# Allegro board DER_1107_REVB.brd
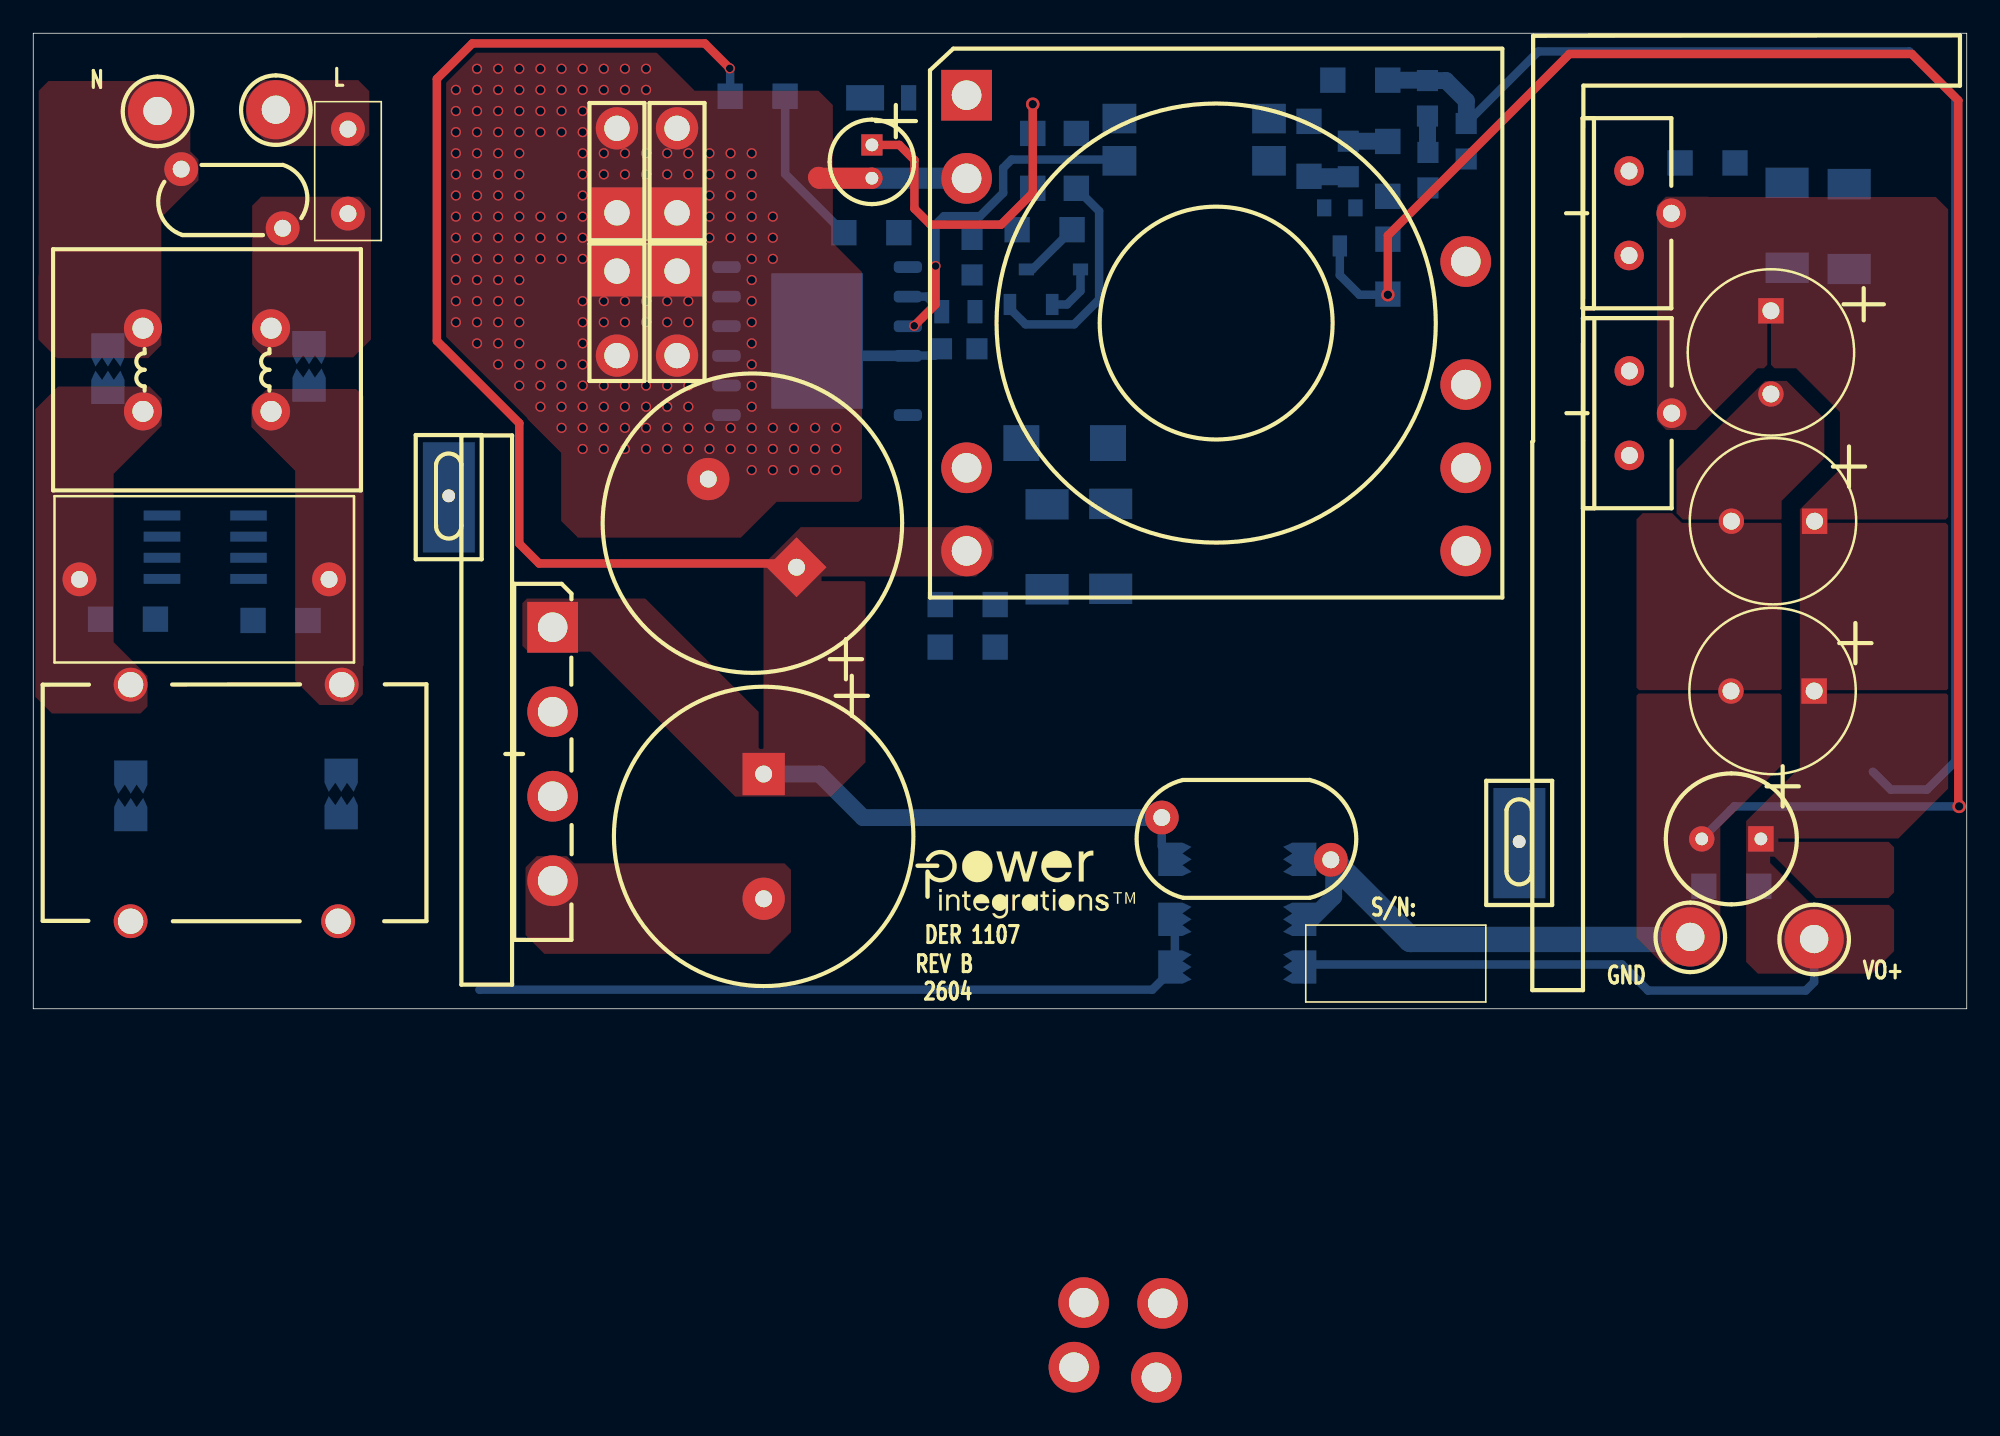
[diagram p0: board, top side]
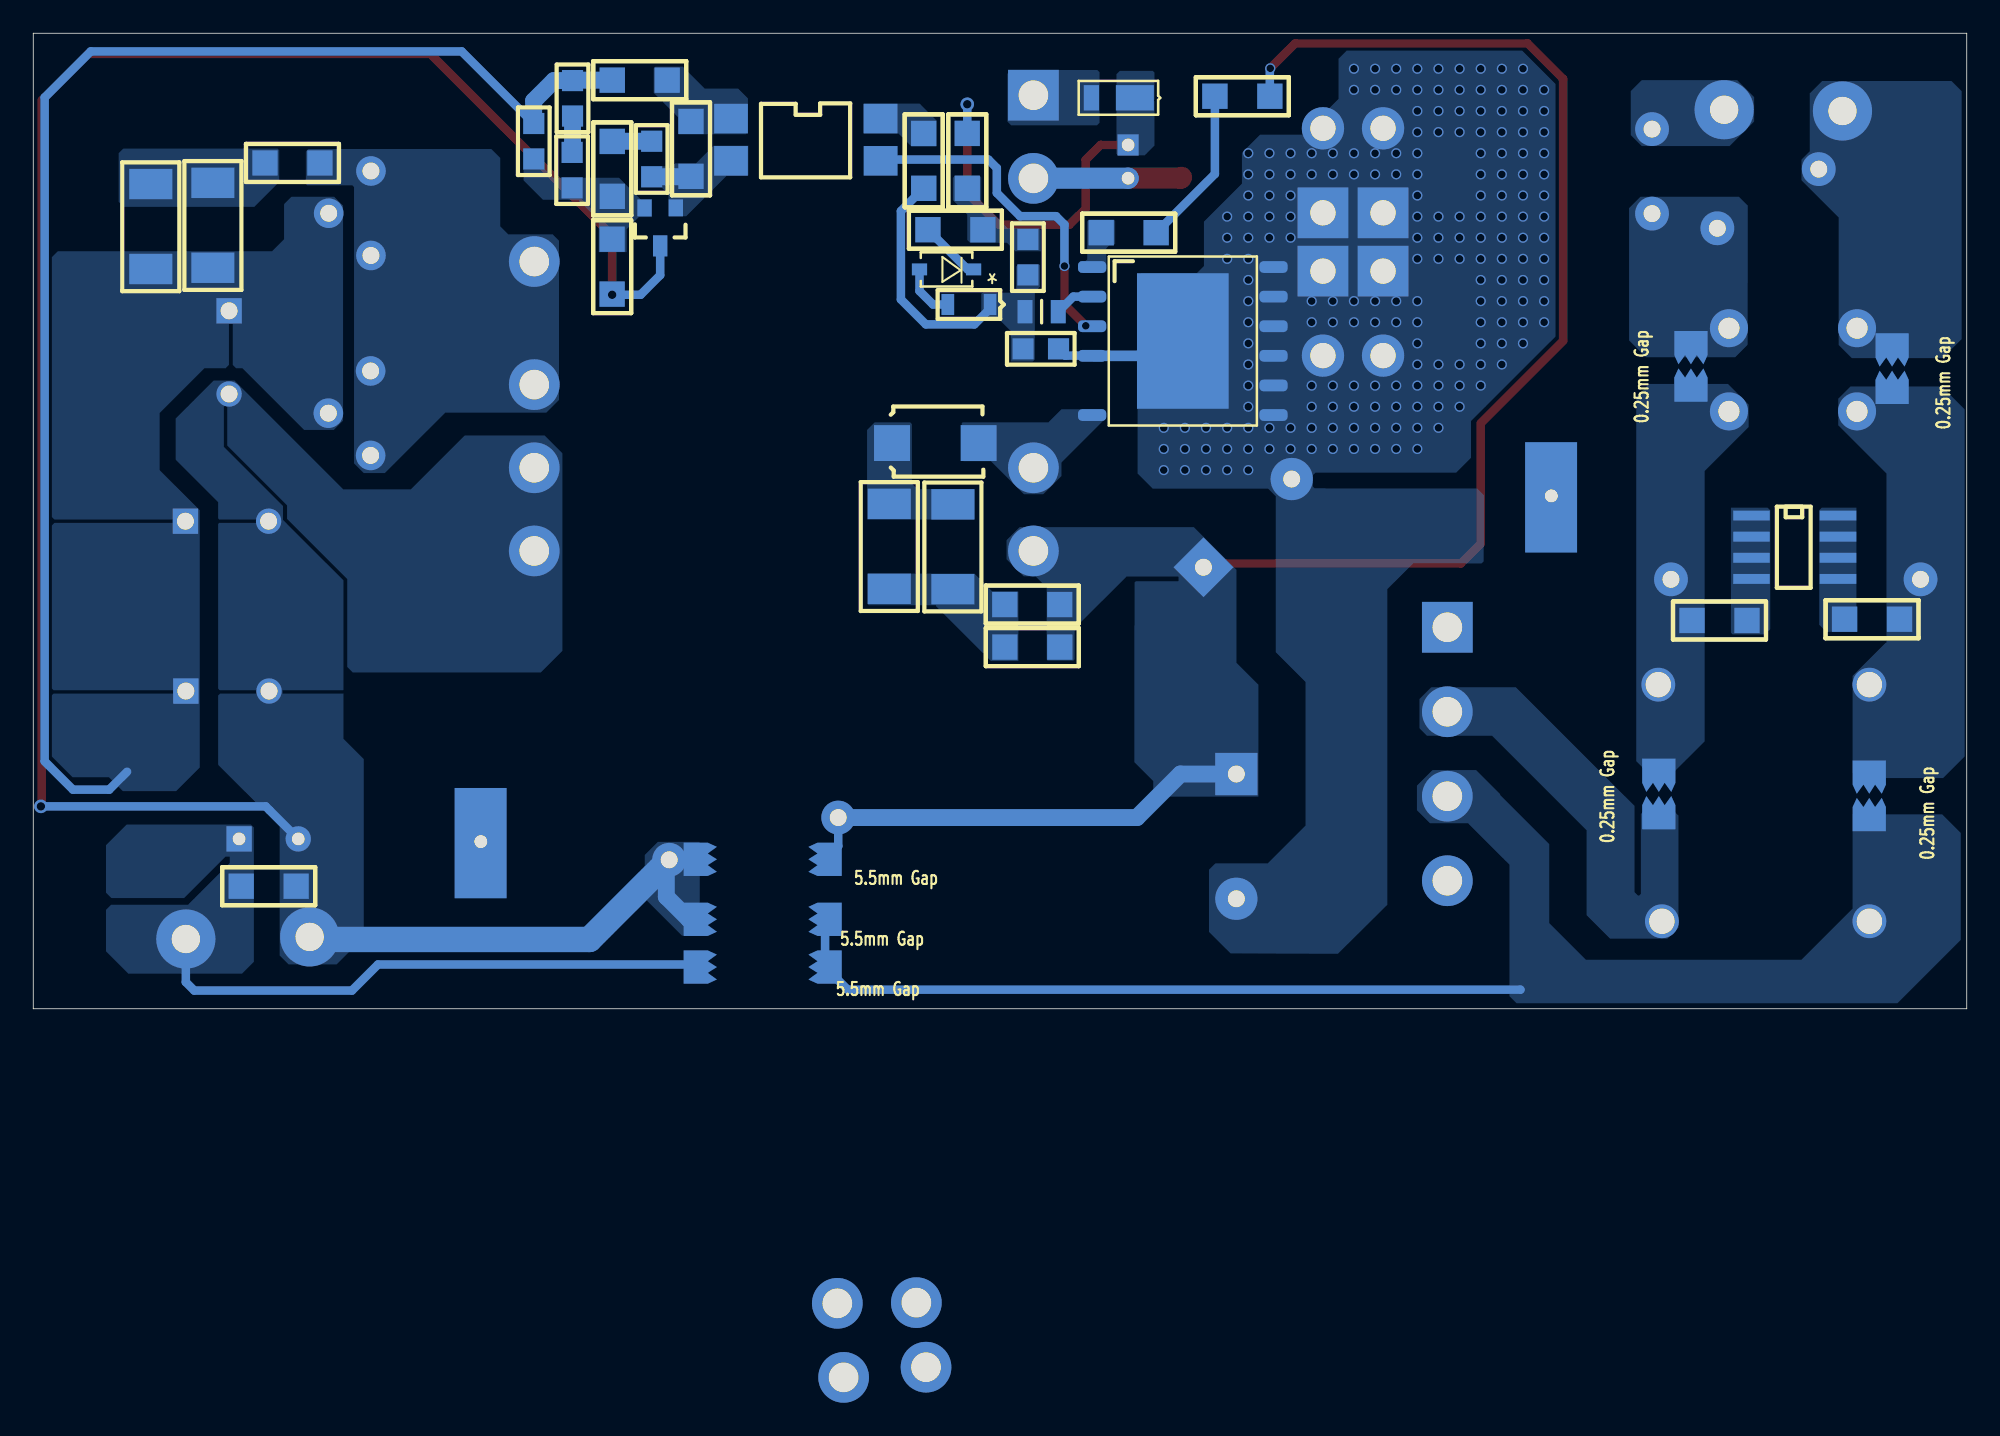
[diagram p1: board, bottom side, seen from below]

Outline 116.2 x 58.65 mm; copper layers: TOP, BOTTOM. Coordinates in mm from the lower left corner of the outline.
Outline path: 0,58.65 116.2,58.65 116.2,0 0,0 0,58.65

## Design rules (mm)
constraint set DEFAULT: min track width 0.508

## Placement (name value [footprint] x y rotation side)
BR1  GBU8K-BP  [PIDAXBRIDGEGBU8]  31.22 22.94 270 top
C1  0.68 uF  [PI_NPCAP18X10X16P1D40]  2.78 25.82 0 top
C3  180 uF  [PIPOLCAPCLYD18MM040]  43.9 10.36 270 top
C4  180 uF  [PIPOLCAPCLYD18MM040]  43.22 29.19 135 top
C6  0.47 uF  [PISMC0805]  56.72 39.67 180 bottom
C7  4700 pF  [PISMC1206]  54.51 24.3 0 bottom
C8  47 uF  [PIPOLCAPCLYD200LS80030]  50.4 51.93 270 top
C9  680 pF  [PISMC1206]  98.98 50.85 0 bottom
C10  560 uF  [PIPOLCAPCLYD10MM040]  104.44 41.96 270 top
C11  560 uF  [PIPOLCAPCLYD10MM040]  107.06 29.31 180 top
C12  10 nF  [PISMC0805]  79.04 50.02 90 bottom
C13  150 uF  [PIPOLCAPCLYD320LS140030]  103.84 10.21 180 top
C14  10 nF  [PISMC0805]  83.82 49.35 90 bottom
C15  560 uF  [PIPOLCAPCLYD10MM040]  107.04 19.1 180 top
C16  10 uF  [PISMC1206]  100.41 7.37 0 bottom
CY1  2.2 nF  [PINPYCAPRAD540X290LS400040]  67.83 11.49 0 top
D1  S2M  [PISMSMB]  64.59 34.01 180 bottom
D3  BAV21WS-7-F  [PISMSOD323]  58.7 42.34 0 bottom
D4  DFLR1200-7  [PISMDDFLR120012]  49.97 54.77 180 bottom
D5  V20202C-M3/4W  [PIDVTO2203VF1]  95.91 47.83 90 top
D6  V20202C-M3/4W  [PIDVTO2203VF1]  95.93 35.81 90 top
F1  5 A  [PI_RST_MICROFUSE]  18.91 52.89 270 top
L1  350 uH  [PIIND4P_18P5X14P5MMD050]  10.44 38.41 0 top
L2  10 mH  [PI_TOROID_BALUN_1]  18.55 5.26 90 top
L3  42 Ohm@100MHz  [INDC2012X105N]  55.6 41.91 180 bottom
NOREF  -  []  0 58.65 0 top
NOREF#2  -  []  -232.54 -144.86 0 top
NOREF#3  -  []  0 0 90 top
NOREF#4  -  []  53.04 9.98 0 top
NOREF#5  -  []  53.72 -90.37 0 top
R1  1 M  [PISMR1206]  16.51 23.34 180 bottom
R2  1 M  [PISMR1206]  7.34 23.42 180 bottom
R3  4.02M  [PISMR1206]  41.88 54.86 0 bottom
R4  4.02M  [PISMR1206]  48.72 46.66 0 bottom
R5  470 k  [PISMR1206]  54.51 21.74 0 bottom
R6  20  [PISMR2010]  60.93 25.22 90 bottom
R7  20  [PISMR2010]  64.76 25.25 90 bottom
R8  3.30 k  [PISMR0805]  56.43 46.25 270 bottom
R9  47.0  [PISMR1206]  59.13 46.84 0 bottom
R10  20  [PISMR2010]  109.14 44.48 90 bottom
R11  20  [PISMR2010]  105.41 44.55 90 bottom
R12  3.01 k  [PISMR1206]  81.41 55.83 180 bottom
R13  1.0 k  [PISMR1206]  76.67 53.35 270 bottom
R14  20.0 k  [PISMR1206]  81.41 48.84 90 bottom
R15  86.6 k  [PISMR0805]  86.12 53.22 270 bottom
R16  10 k  [PISMR1206]  81.41 46.27 270 bottom
R17  0.0  [PISMR1206]  60.07 49.33 90 bottom
R18  0.0  [PISMR1206]  62.69 49.33 90 bottom
R19  10 k  [PISMR0805]  83.79 55.8 270 bottom
RV1  275 Vac  [PIDISC350X160LS210X140040]  14.99 46.92 180 top
SG1  5.5mm gap  [PI_SPARK_GAP_5P5MM]  72.37 8.98 0 bottom
SG2  5.5mm gap  [PI_SPARK_GAP_5P5MM]  72.37 5.38 0 bottom
SG3  5.5mm gap  [PI_SPARK_GAP_5P5MM]  72.37 2.51 0 bottom
SG4  0.25mm gap  [PI_SPARK_GAP_0P25MM]  18.51 12.91 270 bottom
SG5  0.25mm gap  [PI_SPARK_GAP_0P25MM]  5.86 12.8 270 bottom
SG6  0.25mm gap  [PI_SPARK_GAP_0P25MM]  16.58 38.62 270 bottom
SG7  0.25mm gap  [PI_SPARK_GAP_0P25MM]  4.49 38.49 270 bottom
T1  PQ32/30  [PI_BBN_TDKBPQ32_30_12P]  71.09 41.22 0 top
TAB1  CON2  [PI_CONN_QC_TAB_2PIN_LS200]  38.69 47.85 0 top
TAB2  CON2  [PI_CONN_QC_TAB_2PIN_LS200]  35.08 47.85 0 top
TAB3  CON2  [PI_CONN_QC_TAB_2PIN_LS200]  35.08 44.35 180 top
TAB4  CON2  [PI_CONN_QC_TAB_2PIN_LS200]  38.69 44.35 180 top
TE1  Terminal, Eyelet, Zierick 190  [PI_ZIERICK190_EYELET]  24.97 30.84 90 top
TE2  Terminal, Eyelet, Zierick 190  [PI_ZIERICK190_EYELET]  89.31 10.05 90 top
TP1  BLK  [PITPKEYSTONE125X125]  14.58 54.05 0 top
TP2  WHT  [PITPKEYSTONE125X125]  7.47 53.98 0 top
TP3  RED  [PITPKEYSTONE125X125]  107.04 4.19 0 top
TP4  BLK  [PITPKEYSTONE125X125]  99.59 4.32 0 top
U1  CAP200DG  [PI_IC_SMD_SO8_CAPZERO]  12.94 29.65 270 bottom
U2  TOP7078K  [PI_ESOP-12B]  47.11 40.14 270 bottom
U3  LTV-817S-D  [PI_4_SMD_GW_1]  74.27 53.52 270 bottom
U4  LM431BIM3/NOPB  [PISMSOT23123]  79.47 48.15 0 bottom
VR1  MMSZ5246BT1G  [PISM_SOD-123]  61.32 44.45 0 bottom

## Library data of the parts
BR1 = DISCRETE BRIDGE_+~~-: alternate symbols: (pidaxbridgegbu8_horz)
C1 = CAP NP: alternate symbols: (pi_npcap18x10x16p1D40H); room: 1
C3 C4 = CAP POL: alternate symbols: (pipolcapclyd18x40mm040)
C6 C12 C14 = CAP NP: alternate symbols: (Unisem_RMCF0805UL)
C7 C9 = CAP NP: tolerance: 10
C8 = CAP POL: alternate symbols: (pipolcapclyd200ls80030h); tolerance: 20
C10 C11 C15 = CAP POL: alternate symbols: (pipolcapcyld400ls2000401000h)
C13 = CAP POL: alternate symbols: (pipolcapclyd320ls140030430h); tolerance: 20
C16 = CAP NP: alternate symbols: (pismc1206_1)
CY1 = CAP NP
D1 D4 = DIODE
D3 = DIODE: alternate symbols: (SOD323_UL_IPC,pismsod323_1)
D5 D6 = DS_DUAL_CK_AKA: alternate symbols: (pidvto2203,pidvto2203h)
F1 = FUSE: alternate symbols: (pirstmicrofusehoz); room: 1
L1 = CMC_ 4P_14_23
L2 = TORRID 4P_12_34
L3 = INDUCTOR_BEAD
R1 R2 R5-R7 R9-R14 R16-R18 = R
R3 R4 = R: alternate symbols: (pismr1206_1)
R8 R15 R19 = R: alternate symbols: (Unisem_RMCF0805UL)
RV1 = VARISTOR: alternate symbols: (pi_disc_354x220_ls220x10_040_h); room: 1
SG1-SG7 = SPARK_GAP
T1 = BPQ32/30_12P/GENERIC
TAB1-TAB4 = CON1_2P_TAB
TE1 TE2 = TERM EYLT
TP1-TP4 = TESTPOINT: alternate symbols: (TP_5010-14)
U1 = CAPZero: room: 1
U2 = TOPSwitch-GaN_eSOP12B
U3 = OPTO_A_B: alternate symbols: (pi_4_smd_gw)
U4 = TL431/SOT-23_CAR
VR1 = DIODE_ZENER

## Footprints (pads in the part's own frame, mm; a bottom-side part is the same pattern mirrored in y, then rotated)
INDC2012X105N
  rect 0.9x1.4 smd: 1(-1,0) 2(1,0)
PI_4_SMD_GW_1
  rect 1.778x2.032 smd: 1(0,0) 2(2.54,0) 3(2.54,8.992) 4(0,8.992)
PI_BBN_TDKBPQ32_30_12P
  rect 3.048x3.048 hole 1.778: 1(-15,13.7)
  round 3.048 hole 1.778: 2(-15,8.7) 3(-3.214,-58.936) 4(-7.964,-58.894) 5(-15,-8.7) 6(-15,-13.7) 7(15,-13.7) 8(15,-8.7) 9(15,-3.7) 10(15,3.7) 11(-8.546,-62.776) 12(-3.593,-63.389)
PI_CONN_QC_TAB_2PIN_LS200
  rect 3.048x3.048 hole 1.524: 1(0,0)
  round 2.54 hole 1.524: 2(0,5.08)
PI_ESOP-12B
  rrect 0.71x1.7 smd: 1(-4.45,-5.45) 2(-2.67,-5.45) 3(-0.89,-5.45) 4(0.89,-5.45) 6(4.45,-5.45) 7(4.45,5.45) 8(2.67,5.45) 9(0.89,5.45) 10(-0.89,5.45) 11(-2.67,5.45) 12(-4.45,5.45)
  rect 8.15x5.51 smd: 13(0,0)
PI_IC_SMD_SO8_CAPZERO
  rect 0.599x2.2 smd: 1(0,0) 2(1.27,0) 3(2.54,0) 4(3.81,0) 5(3.81,5.199) 6(2.54,5.199) 7(1.27,5.199) 8(0,5.199)
PI_NPCAP18X10X16P1D40
  round 2.032 hole 1.016: 1(0,0) 2(15,0)
PI_RST_MICROFUSE
  round 2.032 hole 1.016: 1(0,0) 2(5.08,0)
PI_SPARK_GAP_0P25MM
  custom 0.5x0.5 smd: 1(-1.125,0) 2(1.125,0)
PI_SPARK_GAP_5P5MM
  custom 0.5x0.5 smd: 1(-3.75,0) 2(3.75,0)
PI_TOROID_BALUN_1
  round 2.032 hole 1.524: 1(14.224,0.013) 2(0,0.229) 3(14.224,12.7) 4(0,12.7)
PI_ZIERICK190_EYELET
  round 0.762 hole 0.762: 1(0,0)
PIDAXBRIDGEGBU8
  rect 3.048x3.048 hole 1.778: 1(0,0)
  round 3.048 hole 1.778: 2(5.08,0) 3(10.16,0) 4(15.24,0)
PIDISC350X160LS210X140040
  round 2.032 hole 1.016: 1(0,0) 2(6.096,-3.556)
PIDVTO2203VF1
  round 1.778 hole 1.016: 1(-2.54,0) 2(0,-2.54) 3(2.54,0)
PIIND4P_18P5X14P5MMD050
  round 2.286 hole 1.27: 1(-3.85,-2.5) 2(3.85,-2.5) 3(3.85,2.5) 4(-3.85,2.5)
PINPYCAPRAD540X290LS400040
  round 2.032 hole 1.016: 1(0,0) 2(10.16,-2.54)
PIPOLCAPCLYD10MM040
  rect 1.524x1.524 hole 1.016: 1(0,0)
  round 1.524 hole 1.016: 2(5,0)
PIPOLCAPCLYD18MM040
  rect 2.54x2.54 hole 1.016: 1(-3.75,0)
  round 2.54 hole 1.016: 2(3.75,0)
PIPOLCAPCLYD200LS80030
  rect 1.27x1.27 hole 0.762: 1(0,0)
  round 1.27 hole 0.762: 2(2,0)
PIPOLCAPCLYD320LS140030
  rect 1.524x1.524 hole 0.762: 1(0,0)
  round 1.524 hole 0.762: 2(3.556,0)
PISM_SOD-123
  rect 0.914x0.711 smd: 1(-1.626,0) 2(1.626,0)
PISMC0805
  rect 1.27x1.27 smd: 1(0,0) 2(2.134,0)
PISMC1206
  rect 1.524x1.524 smd: 1(0,0) 2(3.302,0)
PISMDDFLR120012
  rect 2.286x1.524 smd: 1(-0.025,0)
  rect 0.914x1.524 smd: 2(-2.642,0)
PISMR0805
  rect 1.27x1.27 smd: 1(0,0) 2(2.134,0)
PISMR1206
  rect 1.524x1.524 smd: 1(0,0) 2(3.302,0)
PISMR2010
  rect 1.829x2.591 smd: 1(0,0) 2(5.105,0)
PISMSMB
  rect 2.159x2.159 smd: 1(0,0) 2(5.207,0)
PISMSOD323
  rect 0.762x1.27 smd: 1(0,0) 2(2.54,0)
PISMSOT23123
  rect 0.864x1.016 smd: 1(-1.88,0) 3(0,0)
  rect 0.864x1.27 smd: 2(-0.94,2.286)
PITPKEYSTONE125X125
  round 3.556 hole 1.702: 1(0,0)

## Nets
PGND: BR1.4 C3.2 C4.2 C6.2 C8.2 T1.2 TAB1.1 TAB1.2 TAB2.1 TAB2.2 TAB3.1 TAB3.2 TAB4.1 TAB4.2 U2.4 U2.7 U2.8 U2.9 U2.10 U2.11 U2.12 U2.13
BR: BR1.3(AC2) L2.4 SG2.1 SG3.1 SG5.2
N1180572: C9.1 D5.1 D5.3 D6.1 D6.3 T1.9 T1.10
N1180580: C9.2 R10.2 R11.2
N1180640: BR1.1 C3.1 C4.1 C7.1 CY1.1 R3.1 R5.1 SG1.1 T1.6
N1180772: C10.1 C11.1 C13.1 C15.1 C16.2 D5.2(CATHODE) D6.2(CATHODE) R10.1 R11.1 R12.1 R15.1 R19.1 SG3.2 TP3.1
N1181018: C10.2 C11.2 C13.2 C15.2 C16.1 CY1.2 R16.2 SG1.2 SG2.2 T1.7 T1.8 TP4.1 U4.2
N1181144: R3.2 R4.1
N1181148: D1.2 T1.5 U2.6
N1181266: C8.1 D4.1 R17.2
N1181270: R12.2 R13.1 U3.1
N1181336: C14.1 R14.1 R15.2 R16.1 U4.3(VREF)
N1181354: R4.2 U2.1
N1181442: C12.1 R13.2 U3.2 U4.1
N1193924: D3.2 VR1.2
N1193928: R9.2 VR1.1
N11509583: C1.2 L1.2 L2.1 R1.1 SG4.1 SG6.2
N11509663: R1.2 U1.1 U1.2 U1.3 U1.4
N11509667: R2.1 U1.5 U1.6 U1.7 U1.8(NC8)
N11509705: C1.1 L1.1 L2.3 R2.2 SG5.1 SG7.2
N11509765: F1.2 L1.3 RV1.1 SG6.1
N11509809: L1.4 RV1.2 SG7.1 TP2.1
N11511065: BR1.2 L2.2 SG4.2
N11514098: C12.2 R14.2
N11565135: C7.2 R5.2 R6.1 R7.1
N11566250: F1.1 TP1.1
N11596495: D1.1 R6.2 R7.2
N12575460: R8.1 R9.1 R17.1
N12576026: C6.1 D3.1 L3.1 R8.2 R18.1
N12620029: TE1.1
N12620119: TE2.1
N12646059: L3.2 U2.2
N12657145: R18.2 U3.4
N12660745: D4.2 T1.1
N12661914: U2.3 U3.3(E)
N12671781: C14.2 R19.2

Pads without a net: T1 3 4 11 12

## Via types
v1: diameter 0.813, hole 0.508, TOP to BOTTOM, 3 vias
v2: diameter 0.61, hole 0.457, TOP to BOTTOM, 190 vias

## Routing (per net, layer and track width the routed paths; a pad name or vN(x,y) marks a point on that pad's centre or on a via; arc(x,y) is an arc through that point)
PGND: length 16.9
  TOP w1.27: 47.19,49.99 47.25,49.93 C8.2
  BOTTOM w0.508: U2.4 52.58,39.27 54.18,39.27 C6.2
  BOTTOM w0.635: U2.13 48,39.25 U2.4
  BOTTOM w1.27: T1.2 56.08,49.93 C8.2
  vias: v2(25.4,55.24) v2(25.4,53.98) v2(25.4,52.7) v2(25.4,51.44) v2(25.4,50.16) v2(25.4,48.9) v2(25.4,47.62) v2(25.4,46.35) v2(25.4,45.09) v2(25.4,43.81) v2(25.4,42.55) v2(25.4,41.27) v2(26.67,56.52) v2(26.67,55.24) v2(26.67,53.98) v2(26.67,52.7) v2(26.67,51.44) v2(26.67,50.16) v2(26.67,48.9) v2(26.67,47.62) v2(26.67,46.35) v2(26.67,45.09) v2(26.67,43.81) v2(26.67,42.55) v2(26.67,41.27) v2(26.67,40.01) v2(27.94,56.52) v2(27.94,55.24) v2(27.94,53.98) v2(27.94,52.7) v2(27.94,51.44) v2(27.94,50.16) v2(27.94,48.9) v2(27.94,47.62) v2(27.94,46.35) v2(27.94,45.09) v2(27.94,43.81) v2(27.94,42.55) v2(27.94,41.27) v2(27.94,40.01) v2(27.94,38.73) v2(29.21,56.52) v2(29.21,55.24) v2(29.21,53.98) v2(29.21,52.7) v2(29.21,51.44) v2(29.21,50.16) v2(29.21,48.9) v2(29.21,47.62) v2(29.21,46.35) v2(29.21,45.09) v2(29.21,43.81) v2(29.21,42.55) v2(29.21,41.27) v2(29.21,40.01) v2(29.21,38.73) v2(29.21,37.47) v2(30.48,56.52) v2(30.48,55.24) v2(30.48,53.98) v2(30.48,52.7) v2(30.48,47.62) v2(30.48,46.35) v2(30.48,45.09) v2(30.48,38.73) v2(30.48,37.47) v2(30.48,36.2) v2(31.75,56.52) v2(31.75,55.24) v2(31.75,53.98) v2(31.75,52.7) v2(31.75,47.62) v2(31.75,46.35) v2(31.75,45.09) v2(31.75,38.73) v2(31.75,37.47) v2(31.75,36.2) v2(31.75,34.92) v2(33.02,56.52) v2(33.02,55.24) v2(33.02,53.98) v2(33.02,52.7) v2(33.02,51.44) v2(33.02,50.16) v2(33.02,48.9) v2(33.02,47.62) v2(33.02,46.35) v2(33.02,45.09) v2(33.02,42.55) v2(33.02,41.27) v2(33.02,40.01) v2(33.02,38.73) v2(33.02,37.47) v2(33.02,36.2) v2(33.02,34.92) v2(33.02,33.66) v2(34.29,56.52) v2(34.29,55.24) v2(34.29,51.44) v2(34.29,50.16) v2(34.29,42.55) v2(34.29,41.27) v2(34.29,37.47) v2(34.29,36.2) v2(34.29,34.92) v2(34.29,33.66) v2(35.56,56.52) v2(35.56,55.24) v2(35.56,51.44) v2(35.56,50.16) v2(35.56,42.55) v2(35.56,41.27) v2(35.56,37.47) v2(35.56,36.2) v2(35.56,34.92) v2(35.56,33.66) v2(36.83,56.52) v2(36.83,55.24) v2(36.83,51.44) v2(36.83,50.16) v2(36.83,42.55) v2(36.83,41.27) v2(36.83,37.47) v2(36.83,36.2) v2(36.83,34.92) v2(36.83,33.66) v2(38.1,51.44) v2(38.1,50.16) v2(38.1,42.55) v2(38.1,41.27) v2(38.1,37.47) v2(38.1,36.2) v2(38.1,34.92) v2(38.1,33.66) v2(39.37,51.44) v2(39.37,50.16) v2(39.37,42.55) v2(39.37,41.27) v2(39.37,37.47) v2(39.37,36.2) v2(39.37,34.92) v2(39.37,33.66) v2(40.64,51.44) v2(40.64,50.16) v2(40.64,48.9) v2(40.64,47.62) v2(40.64,46.35) v2(40.64,34.92) v2(40.64,33.66) v2(41.91,51.44) v2(41.91,50.16) v2(41.91,48.9) v2(41.91,47.62) v2(41.91,46.35) v2(41.91,34.92) v2(41.91,33.66) v2(43.18,51.44) v2(43.18,50.16) v2(43.18,48.9) v2(43.18,47.62) v2(43.18,46.35) v2(43.18,45.09) v2(43.18,43.81) v2(43.18,42.55) v2(43.18,41.27) v2(43.18,40.01) v2(43.18,38.73) v2(43.18,37.47) v2(43.18,36.2) v2(43.18,34.92) v2(43.18,33.66) v2(43.18,32.38) v2(44.45,47.62) v2(44.45,46.35) v2(44.45,45.09) v2(44.45,34.92) v2(44.45,33.66) v2(44.45,32.38) v2(45.72,34.92) v2(45.72,33.66) v2(45.72,32.38) v2(46.99,34.92) v2(46.99,33.66) v2(46.99,32.38) v2(48.26,34.92) v2(48.26,33.66) v2(48.26,32.38)
BR: length 45.2
  BOTTOM w0.508: 26.82,1.14 26.83,1.15 67.26,1.15 SG3.1 SG2.1
N1180640: length 95.9
  TOP w0.508: v2(41.86,56.54) 40.36,58.04 26.39,58.04 24.26,55.91 24.26,40.16 29.21,35.2 29.21,27.97 30.4,26.77 45.64,26.77 C4.1
  BOTTOM w0.508: SG1.1 67.83,9.77 CY1.1 ; v2(41.86,56.54) 41.88,56.52 R3.1
  BOTTOM w1.016: CY1.1 49.87,11.49 47.26,14.11 C3.1
N1180772: length 119.4
  BOTTOM w0.508: SG3.2 76.27,2.66 95.49,2.66 97.05,1.09 106.53,1.09 107.04,1.6 TP3.1 ; 110.57,14.25 111.64,13.17 113.82,13.17 115.52,14.87 115.52,54.79 112.75,57.56 90.46,57.56 86.13,53.23
  BOTTOM w1.016: R15.1 86.13,53.23 86.13,54.58 84.91,55.8 R19.1 83.77,55.83 R12.1
N1181018: length 138.1
  TOP w0.508: v1(81.41,42.93) 81.41,46.49 92.33,57.4 112.9,57.4 115.7,54.61 115.7,12.22 v1(115.75,12.17)
  BOTTOM w0.508: U4.2 78.53,44.1 79.71,42.93 81.37,42.93 R16.2 v1(81.41,42.93) ; v1(115.75,12.17) 102.23,12.17 C13.2 100.71,10.21 ; SG1.2 76.15,8.95 CY1.2
  BOTTOM w1.016: SG2.2 76.8,5.38 78.16,6.73 78.16,8.78
  BOTTOM w1.524: TP4.1 99.44,4.17 82.77,4.17 CY1.2
N1181144: length 9.7
  BOTTOM w0.508: R4.1 45.19,50.19 R3.2
N1181266: length 21.7
  TOP w0.508: C8.1 52.05,51.93 52.96,51.03 52.96,48.11 53.92,47.14 58.17,47.14 60.07,49.05 v1(60.07,54.38)
  BOTTOM w0.508: v1(60.07,54.38) R17.2 ; 50.72,52.25 C8.1
N1181442: length 2.4
  BOTTOM w1.016: R13.2 76.7,50.02 C12.1
N1193924: length 3.3
  BOTTOM w0.508: D3.2 62.13,42.34 62.94,43.15 VR1.2
N1193928: length 3.7
  BOTTOM w0.508: VR1.1 60.05,44.45 R9.2
N11514098: length 2.4
  BOTTOM w1.016: C12.2 81.4,52.16 R14.2
N12576026: length 13.9
  BOTTOM w0.508: R18.1 64.06,47.96 64.06,42.65 62.56,41.15 59.64,41.15 58.7,42.09 D3.1
N12646059: length 2.4
  BOTTOM w0.508: L3.2 53.7,42.81 U2.2
N12661914: length 20.6
  TOP w0.508: v2(52.95,41.06) 54.23,42.34 v2(54.23,44.65)
  BOTTOM w0.508: U3.3 65.2,51.05 58.8,51.05 58.29,50.55 58.29,49.05 56.9,47.65 54.74,47.65 54.23,47.14 v2(54.23,44.65) ; v2(52.95,41.06) 52.92,41.03 U2.3
N12671781: length 2.2
  BOTTOM w1.016: R19.2 83.79,51.51 C14.2

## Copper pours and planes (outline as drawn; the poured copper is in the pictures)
PGND on TOP: 29.59,8.51 29.59,4.42 30.71,3.3 44.25,3.3 45.54,4.6 45.54,8.36 45.16,8.74 32.51,8.74 32.08,9.17 30.25,9.17
PGND on TOP: 42.52,28.32 44.68,30.48 49.61,30.48 49.81,30.68 49.81,44.3 48.06,46.05 48.06,54.33 47.19,55.19 39.75,55.19 37.45,57.49 26.63,57.49 24.82,55.68 24.82,40.34 31.72,33.43 31.72,29.34 32.74,28.32
PGND on BOTTOM: 49.63,44.22 46.28,44.22 45.85,44.65 45.85,47.32 43.56,49.61 43.56,51.46 42.47,52.55 39.9,52.55 37.76,54.7 37.76,57.11 37.26,57.61 26.72,57.61 24.71,55.6 24.71,40.41 29.79,35.33 29.79,33.12 30.68,32.23 39.14,32.23 39.29,32.08 39.29,31.39 39.19,31.29 38.56,31.29 38.54,31.28 29.4,31.28 29.03,30.91 29.03,26.9 29.16,26.77 33.27,26.77 34.82,25.22 34.82,6.25 37.8,3.3 44.25,3.33 45.54,4.62 45.54,8.36 45.16,8.74 42.01,8.74 39.74,11.01 39.74,19.65 41.53,21.44 41.53,30.81 41.99,31.27 48.92,31.27 49.83,32.18 49.83,44.02
BR on BOTTOM: 27.05,0.33 27.48,0.76 27.48,8.66 29.97,11.15 32.26,11.15 33.05,11.94 33.05,13.41 32.11,14.35 29.49,14.35 28.04,12.9 28.04,12.85 25.1,9.91 25.1,5.16 22.89,2.95 9.93,2.95 6.86,6.02 6.86,11.68 1.47,11.68 0.36,10.57 0.36,4.14 4.17,0.33
N1180572 on BOTTOM: 88.67,51.69 99.67,51.69 99.82,51.54 99.82,49.58 99.75,49.5 97.03,49.5 96.93,49.4 96.93,32.79 96.34,32.21 95.07,32.21 91.44,35.84 85.37,35.84 84.61,36.6 84.61,46.18 84.99,46.56 87.66,46.56 88.14,47.04 88.14,51.16
N1180580 on BOTTOM: 101.52,51.71 110.79,51.71 111.07,51.44 111.07,48.51 110.77,48.21 102.92,48.21 101.42,49.71 101.42,51.61
N1180640 on TOP: 29.74,21.46 33.48,21.46 42.19,12.75 47.96,12.75 50.01,14.81 50.01,25.63 49.94,25.7 47.4,25.7 47.37,25.73 47.37,25.96 47.4,25.99 56.66,25.99 57.72,27.05 57.72,28.16 56.92,28.96 46.13,28.96 43.85,26.68 43.89,26.64 43.89,15.67 43.84,15.62 43.68,15.62 43.6,15.7 43.6,17.84 36.78,24.66 29.67,24.66 29.39,24.38 29.39,21.82
N1180640 on BOTTOM: 50.5,25.98 47.4,25.98 47.37,25.96 47.37,25.73 47.4,25.7 49.94,25.7 50.01,25.63 50.01,23.06 50.03,23.05 50.03,14.82 48.9,13.69 48.9,12.85 48.79,12.75 42.57,12.75 42.57,19.48 43.89,20.8 43.89,26.39 46.46,28.96 56.92,28.96 57.71,28.17 57.71,27.03 56.68,26 55.97,26 55.3,25.32 55.3,20.98 55.24,20.93 53.7,20.93 53.62,21.01 53.62,22.86
N1180772 on TOP: 98.12,48.82 100.69,48.82 100.7,48.81 114.34,48.81 115.09,48.06 115.09,29.57 114.94,29.41 107.44,29.41 107.39,29.36 107.39,29.26 107.44,29.21 114.94,29.21 115.09,29.06 115.09,19.25 114.99,19.15 107.62,19.15 107.57,19.1 107.57,19 107.62,18.95 114.99,18.95 115.09,18.85 115.09,13.23 112.09,10.24 104.9,10.24 104.88,10.21 104.88,10.06 104.9,10.03 111.51,10.03 111.84,9.7 111.84,6.99 111.51,6.65 107.14,6.65 104.65,9.14 104.39,9.14 104.39,8.76 106.91,6.25 111.53,6.25 111.84,5.94 111.84,3.45 110.49,2.11 103.66,2.11 102.95,2.82 102.95,11.28 106.17,14.5 106.17,30.02 108.58,32.44 108.58,35.86 105.94,38.51 104.65,38.51 104.44,38.71 104.44,41.35 104.37,41.43 104.29,41.43 104.22,41.35 104.22,38.71 104.01,38.51 103.63,38.51 99.92,34.8 98.15,34.8 97.59,35.36 97.59,48.29
N1180772 on BOTTOM: 103.12,11.07 110.59,11.07 111.84,9.83 111.84,6.99 111.51,6.65 107.14,6.65 104.65,9.14 104.39,9.14 104.39,8.76 106.91,6.25 111.53,6.25 111.84,5.94 111.84,3.45 110.49,2.11 103.66,2.11 102.95,2.82 102.95,10.9
N1180772 on BOTTOM: 98.12,48.82 100.69,48.82 101.13,48.37 101.13,46.27 101.85,45.54 114.73,45.54 115.09,45.19 115.09,29.57 114.94,29.41 107.44,29.41 107.39,29.36 107.39,29.26 107.44,29.21 114.94,29.21 115.09,29.06 115.09,19.25 114.99,19.15 107.49,19.15 107.44,19.1 107.44,19.02 107.52,18.95 114.99,18.95 115.09,18.85 115.09,15.16 113.84,13.92 111.66,13.92 110.82,13.08 107.62,13.08 106.2,14.5 106.2,29.97 108.61,32.38 108.61,35.81 105.92,38.51 104.65,38.51 104.44,38.71 104.44,41.35 104.37,41.43 104.29,41.43 104.22,41.35 104.22,38.71 104.01,38.51 103.63,38.51 99.92,34.8 98.15,34.8 97.59,35.36 97.59,48.29
N1181018 on TOP: 104.09,37.74 105.38,37.74 107.65,35.48 107.65,33.1 105.08,30.53 105.08,29.46 105.03,29.41 102.59,29.41 102.54,29.36 102.54,29.26 102.59,29.21 105.03,29.21 105.08,29.16 105.08,19.23 105,19.15 102.54,19.15 102.49,19.1 102.49,19 102.54,18.95 104.98,18.95 105.08,18.85 105.08,14.63 101.4,10.95 101.4,3.2 100.86,2.67 97.97,2.67 96.35,4.28 96.35,18.82 96.48,18.95 101.57,18.95 101.6,18.97 101.6,19.13 101.57,19.15 96.51,19.15 96.35,19.3 96.35,29.43 96.72,29.79 98.5,29.79 99.09,29.21 101.52,29.21 101.57,29.26 101.57,29.36 101.52,29.41 99.14,29.41 98.77,29.78 98.77,32.42
N1181018 on BOTTOM: 76.15,10.03 78.66,10.03 79.45,9.25 79.45,6.63 77.22,4.39 76.35,4.39 76.15,4.6
N1181018 on BOTTOM: 104.11,37.77 105.36,37.77 107.65,35.48 107.65,33.01 105.09,30.45 105.09,29.48 105.03,29.41 102.62,29.41 102.57,29.36 102.57,29.29 102.64,29.21 105.03,29.21 105.09,29.15 105.09,19.23 105.08,19.23 105,19.15 102.54,19.15 102.49,19.1 102.49,19 102.54,18.95 104.98,18.95 105.09,18.83 105.09,14.67 101.4,10.97 101.4,3.2 100.86,2.67 97.97,2.67 96.34,4.29 96.34,15.01 97.56,16.23 97.56,18.95 101.22,18.95 101.22,19.15 97.56,19.15 97.56,25.76 101.19,29.39 101.19,30.23 104.75,33.78 104.75,36.2 104.7,36.25 104.57,36.25 104.55,36.22 104.55,33.86 100.95,30.26 100.95,29.45 97.33,25.83 97.33,20.55 97,20.22 85.7,20.22 84.4,21.51 84.4,33.4 85.47,34.47 90.27,34.47 93.51,31.23 97.57,31.23
N1181148 on BOTTOM: 51.92,36.04 54.41,36.04 55.19,35.26 60.35,35.26 60.4,35.2 60.4,33.02 60.3,32.92 58.65,32.92 56.67,30.94 55.5,30.94 54.41,32.03 54.41,32.84 51.77,35.48 51.77,35.89
N1181266 on BOTTOM: 51.1,51.41 51,51.31 49.4,51.31 48.82,51.89 48.82,54.56 48.87,54.61 48.82,54.66 48.82,56.29 48.92,56.39 50.9,56.39 51.1,56.18
N1181270 on BOTTOM: 75.84,55.32 73.84,55.32 73.25,54.74 73.25,52.7 73.38,52.58 77.42,52.58 77.42,53.57 78.92,55.07 78.92,56.54 78.82,56.64 77.17,56.64
N1181336 on BOTTOM: 79.04,48.67 79.71,48.67 81,49.96 84.94,49.96 85.5,50.52 85.5,51.71 86.74,51.71 86.74,49.81 85.57,48.64 84.05,48.64 84.02,48.62 83.44,48.62 82.22,47.4 82.22,45.49 80.54,45.49 80.54,46.86 79.81,47.6 79.02,47.6 79.02,48.64
N1181354 on BOTTOM: 51.26,47.45 52.76,47.45 52.86,47.35 52.86,45.06 52.96,44.96 53.26,44.96 53.42,44.81 53.42,44.4 53.26,44.25 51.82,44.25 51.71,44.35 51.71,45.72 51.56,45.87 51.31,45.87 51.18,46 51.18,47.37
N1181442 on BOTTOM: 73.23,51.89 75.31,51.89 76.38,50.83 77.65,50.83 77.83,50.65 79.65,50.65 79.68,50.62 79.68,49.38 78.49,49.38 78.46,49.4 78.03,48.97 78.03,47.65 76.96,47.65 74.52,50.09 73.25,50.09 73.23,50.11
N11509583 on TOP: 19.81,20.6 19.86,20.65 19.86,36.8 19.41,37.26 14.05,37.26 13.11,36.32 13.11,34.98 15.74,32.35 15.74,19.72 17.2,18.26 19.18,18.26 19.81,18.9
N11509583 on BOTTOM: 15.75,16.08 17.96,13.87 18.85,13.87 19.86,14.88 19.86,36.78 19.08,37.57 14.35,37.57 13.11,36.32 13.11,34.98 15.75,32.33
N11509663 on BOTTOM: 11.96,30.12 14.17,30.12 14.17,22.61 14.07,22.5 12.12,22.5 11.81,22.81 11.81,29.97
N11509667 on BOTTOM: 8.71,30.12 6.63,30.12 6.63,22.66 8.43,22.66 8.86,23.09 8.86,29.97
N11509705 on TOP: 4.83,32.16 7.72,35.05 7.72,36.68 6.99,37.41 1.5,37.41 0.13,36.04 0.13,18.75 1.12,17.75 6.45,17.75 6.86,18.16 6.86,20.02 4.83,22.05
N11509705 on BOTTOM: 4.83,32.18 7.72,35.08 7.72,36.68 6.99,37.41 1.5,37.41 0.13,36.04 0.13,15.16 1.42,13.87 6.53,13.87 6.86,14.2 6.86,20.02 4.88,22 4.83,22
N11509765 on TOP: 19.61,48.82 13.69,48.82 13.16,48.29 13.16,39.93 13.92,39.17 19.23,39.17 20.29,40.23 20.29,48.13
N11509765 on BOTTOM: 19.61,48.82 13.69,48.82 13.16,48.29 13.16,43.64 13.17,43.62 13.17,39.92 13.92,39.17 19.28,39.17 20.29,40.18 20.29,48.13
N11509809 on TOP: 0.91,55.78 8.69,55.78 9.44,55.03 9.44,51.55 9.93,51.05 9.93,49.81 7.7,47.57 7.7,39.9 6.91,39.12 1.42,39.12 0.3,40.23 0.3,44.07 0.33,44.09 0.33,55.19
N11509809 on BOTTOM: 0.91,55.78 8.69,55.78 9.44,55.03 9.44,51.55 9.93,51.05 9.93,49.81 7.7,47.57 7.7,39.9 6.91,39.12 1.45,39.12 0.3,40.26 0.3,55.17
N11511065 on BOTTOM: 22.85,10.73 28.52,16.41 32.44,16.41 32.89,16.87 32.89,18.62 32.18,19.33 27.1,19.33 19.96,12.19 19.96,7.01 19.76,6.81 19.68,6.81 19.58,6.91 19.58,11.71 19.38,11.91 17.63,11.91 17.32,11.61 17.32,4.88 17.98,4.22 21.44,4.22 22.85,5.63
N11565135 on BOTTOM: 59.64,26.16 66.04,26.16 66.07,26.14 66.07,24.33 65.99,24.26 61.95,24.26 61.95,24.21 58.65,20.9 57,20.9 57,25.07 57.02,25.1 58.57,25.1
N11566250 on TOP, BOTTOM: 13.79,55.83 19.53,55.83 20.19,55.17 20.19,52.53 19.53,51.87 14.25,51.87 12.78,53.34 12.78,54.81
N11596495 on BOTTOM: 63.5,35.26 65.63,35.26 66.09,34.8 66.09,29.44 66.07,29.41 59.64,29.41 59.64,31.24 63.07,31.24 63.4,31.57 63.4,35.15
N12575460 on BOTTOM: 60.81,50.09 59.33,50.09 59.23,49.99 59.23,48.51 57.63,46.91 55.75,46.91 55.65,46.81 55.65,45.54 57.18,45.54 57.68,46.05 59.89,46.05 60.07,46.23 60.07,47.75 60.93,48.62 60.93,49.96
N12576026 on BOTTOM: 55.75,44.75 57,44.75 57.12,44.63 57.12,43.26 57.33,43.05 59.16,43.05 59.23,42.98 59.23,41.76 59.05,41.58 58.29,41.58 57.45,40.74 57.45,38.91 56.13,38.91 56.01,39.04 56.01,43.1 55.7,43.41 55.7,44.7
N12620029 on BOTTOM (solid shape): 26.54,27.43 23.42,27.43 23.42,34.06 26.54,34.06
N12620119 on BOTTOM (solid shape): 90.88,6.64 87.76,6.64 87.76,13.27 90.88,13.27
N12657145 on BOTTOM: 62.93,54.42 61.93,53.42 61.93,51.84 63.42,51.84 64.21,52.63 66.29,52.63 66.32,52.65 66.32,54.38 66.28,54.42
N12660745 on BOTTOM: 52.12,53.26 52.12,56.31 52.25,56.44 57.43,56.44 57.66,56.21 57.66,53.34 57.43,53.11 52.27,53.11

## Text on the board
Ref Des/Silkscreen Top: N | L | REV B | 2604 | DER 1107 | S/N: | GND | VO+
User.5: NONE PLATED SLOTS
User.8: FIGURE | FINISHED_SIZE | 18.0 | 25.0 | 30.0 | 40.0 | 42.0 | 60.0 | 67.0 | 70.0 | DRILL CHART: TOP to BOTTOM | ALL UNITS ARE IN MILS | TOLERANCE_DRILL | +3.0/-3.0 | +0.0/-0.0 | PLATED | QTY | 106 | 4 | 2 | 23 | 1 | 16
